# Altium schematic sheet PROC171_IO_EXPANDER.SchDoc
size 431 x 279 mm; DocumentNumber: 23; SheetNumber: 23; SheetTotal: 27
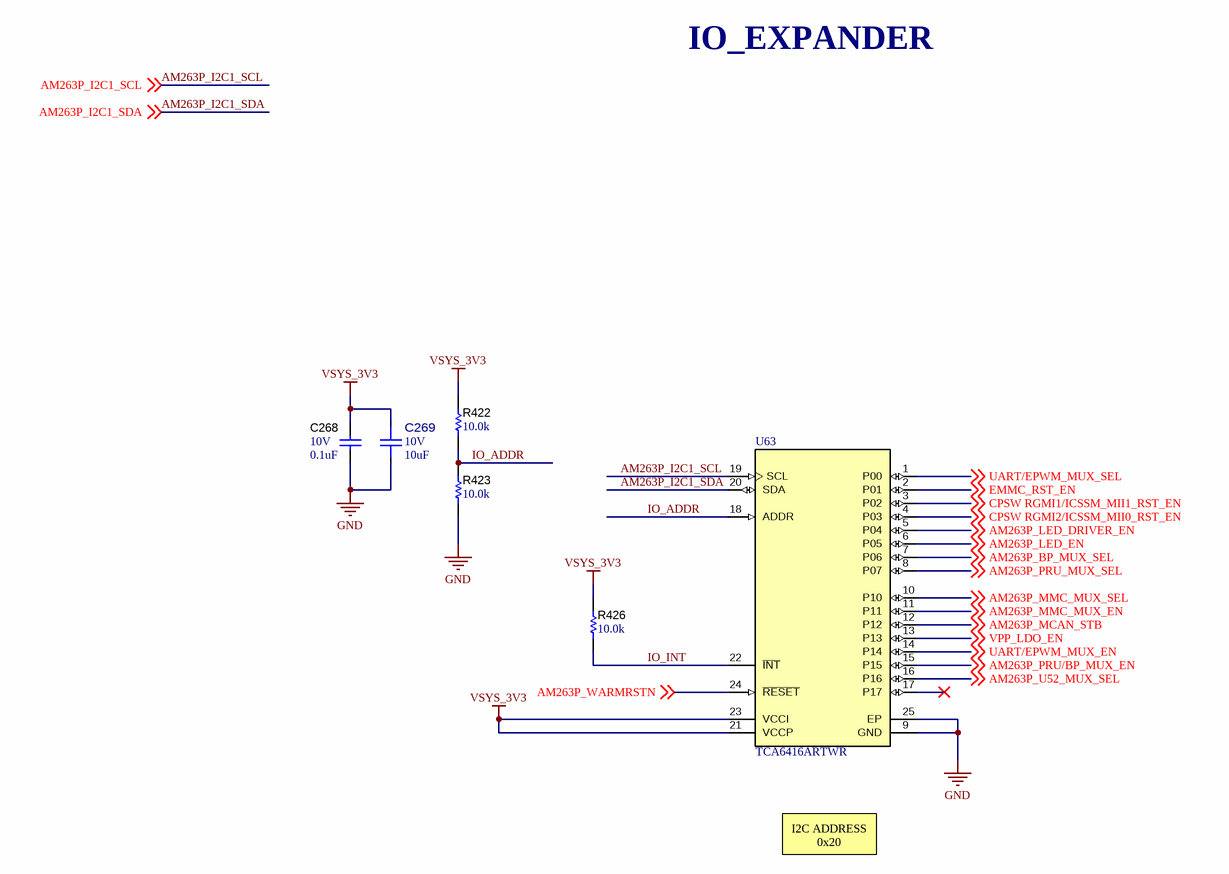
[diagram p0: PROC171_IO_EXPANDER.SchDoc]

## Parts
C268  VDC_V: 10V  ValueDisplayed: 0.1uF  [0402]  (hidden comment: 885012105010)
C269  ValueDisplayed: 10uF  VDC_V: 10V  [FP-KGM05CR51A106MH_0402-MFG]  (hidden comment: KGM05CR51A106MH)
R422  ValueDisplayed: 10.0k  [0402]  (hidden comment: ERJ-2RKF1002X)
R423  ValueDisplayed: 10.0k  [0402]  (hidden comment: ERJ-2RKF1002X)
R426  ValueDisplayed: 10.0k  [0402]  (hidden comment: ERJ-2RKF1002X)
U63  TCA6416ARTWR  [RTW0024B]

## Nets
GND: C268.2 C269.2 R423.1 U63.9(GND) U63.25(EP)
VSYS_3V3: C268.1 C269.1 R422.2 R426.2 U63.21(VCCP) U63.23(VCCI)
AM263P_BP_MUX_SEL: U63.7(P06) ; off-sheet AM263P_BP_MUX_SEL
AM263P_I2C1_SCL: U63.19(SCL) ; off-sheet AM263P_I2C1_SCL
AM263P_I2C1_SDA: U63.20(SDA) ; off-sheet AM263P_I2C1_SDA
AM263P_LED_DRIVER_EN: U63.5(P04) ; off-sheet AM263P_LED_DRIVER_EN
AM263P_LED_EN: U63.6(P05) ; off-sheet AM263P_LED_EN
AM263P_MCAN_STB: U63.12(P12) ; off-sheet AM263P_MCAN_STB
AM263P_MMC_MUX_EN: U63.11(P11) ; off-sheet AM263P_MMC_MUX_EN
AM263P_MMC_MUX_SEL: U63.10(P10) ; off-sheet AM263P_MMC_MUX_SEL
AM263P_PRU/BP_MUX_EN: U63.15(P15) ; off-sheet AM263P_PRU/BP_MUX_EN
AM263P_PRU_MUX_SEL: U63.8(P07) ; off-sheet AM263P_PRU_MUX_SEL
AM263P_U52_MUX_SEL: U63.16(P16) ; off-sheet AM263P_U52_MUX_SEL
AM263P_WARMRSTN: U63.24(~{RESET}) ; off-sheet AM263P_WARMRSTN
CPSW RGMI1/ICSSM_MII1_RST_EN: U63.3(P02) ; off-sheet CPSW RGMI1/ICSSM_MII1_RST_EN
CPSW RGMI2/ICSSM_MII0_RST_EN: U63.4(P03) ; off-sheet CPSW RGMI2/ICSSM_MII0_RST_EN
EMMC_RST_EN: U63.2(P01) ; off-sheet EMMC_RST_EN
IO_ADDR: R422.1 R423.2 U63.18(ADDR)
IO_INT: R426.1 U63.22(~{INT})
UART/EPWM_MUX_EN: U63.14(P14) ; off-sheet UART/EPWM_MUX_EN
UART/EPWM_MUX_SEL: U63.1(P00) ; off-sheet UART/EPWM_MUX_SEL
VPP_LDO_EN: U63.13(P13) ; off-sheet VPP_LDO_EN

Not connected (* = marked no-connect by the designer): U63 17(P17)*

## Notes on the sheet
- IO_EXPANDER
- I2C ADDRESS 0x20

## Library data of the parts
C268 = CMP-0006221-2: CAP, CERM, 0.1 uF, 10 V, +/- 20%, X5R, 0402; Manufacturer: Wurth Elektronik; TaMin_C: -55°C; Polarized: N; SizeAreaWB_mm2: 3; Value1: Unknown; U/M: EA; Value: 0.1uF; TaMax_C: 85°C; SizeZ_mm: 0.6; SizeX_mm: 1; SizeY_mm: 0.5; Cap_F: 100nF; AEC Category: Q200
C269 = CMP-0043010-1: 10 µF ±20% 10V Ceramic Capacitor X5R 0402 (1005 Metric); Manufacturer: KYOCERA AVX; AEC Qualified: No; Cap_F: 10µF; SizeZ_mm: 0.7mm; TempCo: 15%; Value: 10µF
R422 R423 R426 = CMP-0026658-1: RES, 10.0 k, 1%, 0.1 W, 0402; Manufacturer: Panasonic; Power_W: 100mW; TempCo: 100 ppm/C; Value_Code: 10k0; U/M: EA; Value: 10.0k; EIA_Code: E96; Res_ohm: 10k; SizeX_mm: 1; SizeY_mm: 0.5; SizeZ_mm: 0.6; Value2: 0.1W; VDC_V: 50V; AEC Category: Q200
U63 = CMP-0043175-2: Low-Voltage 16-Bit I2C and SMBus I/O Expander, 16 Outputs, 1.65 to 5.5 V, -40 to 85 degC, 24-pin QFN (RTW), Green (RoHS & no Sb/Br); Manufacturer: Texas Instruments; SubFamily: I2C IO Expander; VCC(Max)(V): 5.5; VCC(Min)(V): 1.65; No. of Outputs: 16; fSCLK(Max)(MHz): 400; 5V Tolerant I/O: Yes; I2C Address: 0100 00x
